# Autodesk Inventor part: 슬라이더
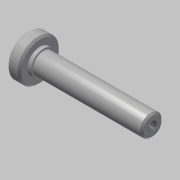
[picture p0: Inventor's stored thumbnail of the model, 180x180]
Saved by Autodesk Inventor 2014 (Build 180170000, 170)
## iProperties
Created: 2011-04
Part Number: 슬라이더
Document SubType Name: Modeling
Designer: 한국산업디자인학원 [http://gmhk.co.kr]
Density: 7.86 g/cm^3
Material: 강철, 연강
Mass: 76.7999 g
Surface Area: 38.1769 cm^2
Volume: 9.77098 cm^3
Appearance: 강철
Author: pww
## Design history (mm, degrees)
sketch "스케치1"
  geometry: L1 (-7, 0)-(63, 0); L2 (63, 0)-(63, 6); L3 (63, 6)-(0, 6); L4 (-7, 0)-(-7, 11.5); L5 (-7, 11.5)-(0, 11.5); L6 (0, 11.5)-(0, 6); 1 further point
  constraints: 12 end point, 3 perpendicular, 2 horizontal, 2 point on line, 1 parallel
  dimensions: "d1" = 70 distance of L1.start L1.end; "d19" = 12 diameter of L3 L1; "d20" = 7 distance of L4.end L5.end; "d21" = 23 diameter of L5 L1
revolve "회전1" stored, may be unused: angle "d4" = 90 deg
chamfer "모따기1" distance "d16" = 1; stored, may be unused: second distance "d17" = 2, angle "d18" = 45 deg
hole "구멍2" diameter "d24" = 4.917; stored, may be unused: countersink angle "d28" = 90 deg, drill point angle "d30" = 118 deg; dims "d22" = 10, "d23" = 10, "d25" = 10, "d26" = 4, "d27" = 2, "d29" = 13
sketch "스케치2"
  geometry: C1 r 7 at (0, 0); 1 further point
  constraints: 1 centre point, 1 coincident
  dimensions: "d31" = 14 diameter of C1
extrude "돌출2" join sketch "스케치2" distance "d32" = 2; taper "d33" = 0 deg
node "솔리드1"
